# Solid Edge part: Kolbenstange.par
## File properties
Author: bmolnar
Last saved by: bmolnar
Revision: 77
Sűrűség: 0,000 kg/m^3
Pontosság: 0,990
Username: bmolnar
Dokumentum tartalom típus: 0
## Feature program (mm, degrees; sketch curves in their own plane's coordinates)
base feature "unnamed BaseFeature 1"
sketch for "unnamed Protrusion 1" plane through (54.2, 0.0012, 0) normal (1, 0, 0) x-axis (0, 0, -1)
  circle centre (0, -0.0012) radius 50
extrude "unnamed Protrusion 1" add finite 21.4 along +normal
sketch for "Kihúzás_2" #1 plane through (54.2, 0.0012, 0) normal (1, 0, 0) x-axis (0, 0, -1)
  circle centre (0, -0.0012) radius 12.5
sketch for "Kihúzás_2" #2 plane through (54.2, 0.0012, 0) normal (1, 0, 0) x-axis (0, 0, -1)
  circle centre (0, -0.0012) radius 50
extrude "Kihúzás_2" add finite 12.85 along -normal
sketch for "Furat_1" plane through (-5, 0.0012, 0) normal (-1, 0, 0) x-axis (0, 0, 1)
  hole centre (0, -0.0012) bore radius 5.053
hole "Furat_1" nominal diameter 12 finite  VBottomAngle = 118 deg; ThreadDepth = 22 mm
chamfer "Letörés_1" setback 1  SetBackValue2 = 45 deg
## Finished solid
Body 1: solid body, 14 faces, 20 edges, 8 vertices.
  Faces by surface: plane 7, cylinder 4, cone 2, torus 1
  Edges by curve: circle 10, line 6, curve on surface 2, ellipse 2
Bounding box of the edges (mm; curved faces can reach further): 80.600 x 100.000 x 100.000, from (-5, -50, -50) to (75.6, 50, 50).
Cylindrical faces by radius (mm): R5.053 x2, R12.5 x1, R50 x1
Conical faces (half-angle, radius in mm at the cone's reference point): 45 deg R6.053 x1, 59 deg R5.053 x1
Toroidal faces (ring radius, tube radius in mm): R10.7 r1.8 x1
Planar faces by outward normal: +x 1, +y 1, -x 2, -y 1, oblique 2
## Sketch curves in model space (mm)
circle centre (54.2, 0, 0) radius 50
circle centre (54.2, 0, 0) radius 12.5
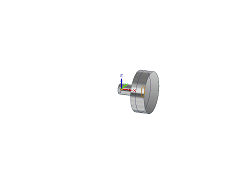
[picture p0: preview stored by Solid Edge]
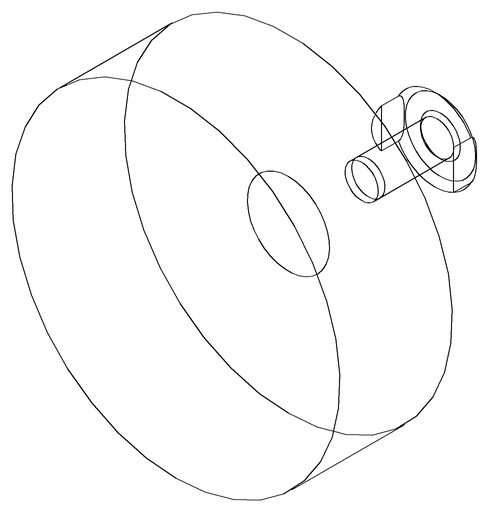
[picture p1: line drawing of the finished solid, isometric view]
